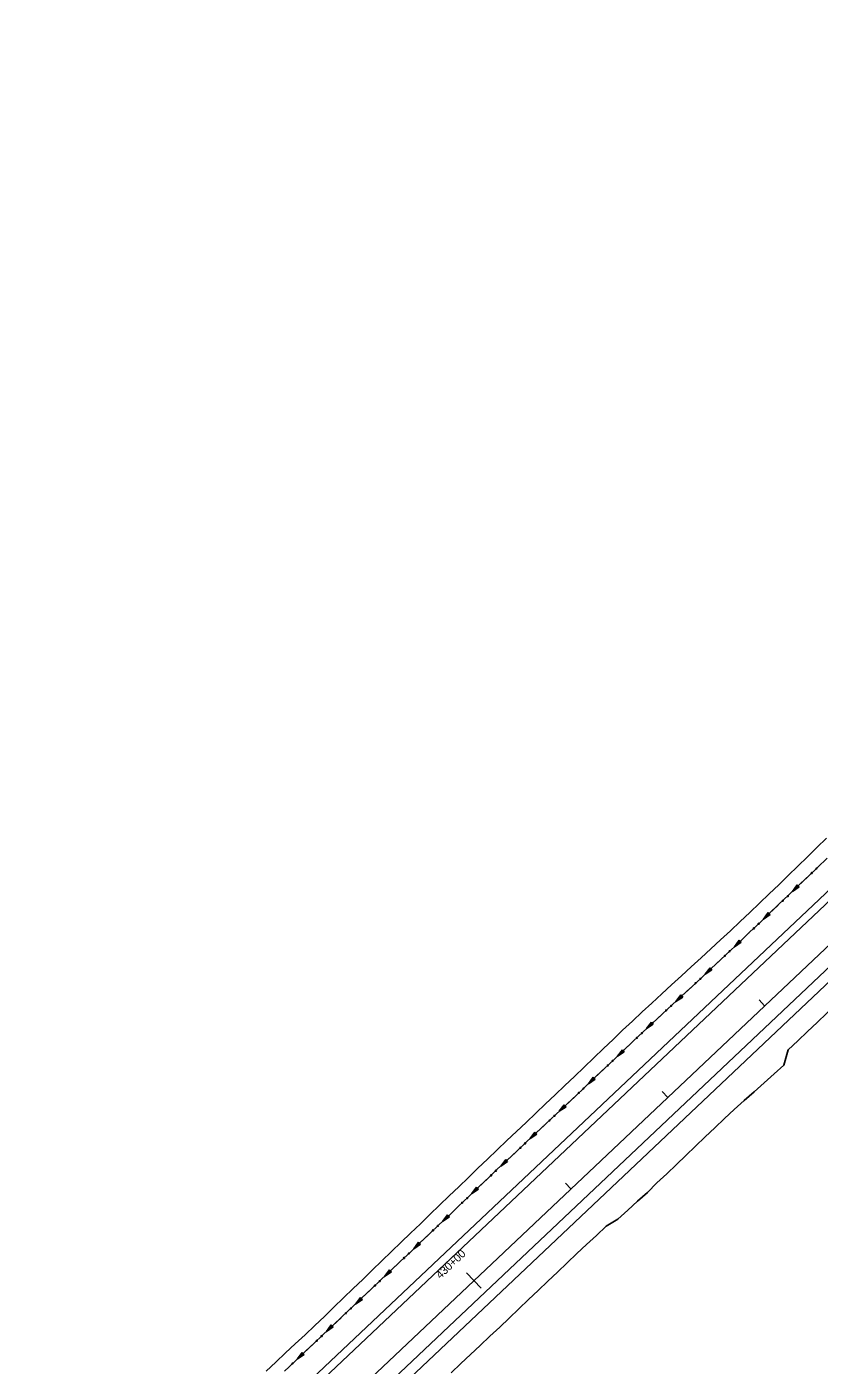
# Model space of a CAD drawing. Extents: x 1375694 to 1433473, y 1931050 to 1967991.
# Drawn here: x 1430411 to 1431005, y 1965367 to 1966371 of the extents above; entities that cross this region are included whole.
import ezdxf

# ---------------------------------------------------------------- set-up
doc = ezdxf.new("R2010")
doc.units = 0
for name, color, linetype in [('62', 7, 'Continuous'), ('R_Horz Alg', 7, 'Continuous'), ('R_Horz Alg Annot', 7, 'Continuous'), ('R_Proposed Const Limits', 7, 'Continuous'), ('R_Proposed Road', 7, 'Continuous')]:
    doc.layers.add(name, color=color, linetype=linetype)

msp = doc.modelspace()

# ---------------------------------------------------------------- linework, layer by layer
at = {"layer": '62'}
for p, q in [((1430989, 1965727.5), (1430985.4, 1965722.6)), ((1430985.4, 1965722.6), (1430990.4, 1965726)), ((1430990.4, 1965726), (1430989, 1965727.5)), ((1430967.2, 1965706.8), (1430963.6, 1965701.9)), ((1430963.6, 1965701.9), (1430968.7, 1965705.3)), ((1430968.7, 1965705.3), (1430967.2, 1965706.8)), ((1430945.5, 1965686.1), (1430941.8, 1965681.2)), ((1430941.8, 1965681.2), (1430946.9, 1965684.6)), ((1430946.9, 1965684.6), (1430945.5, 1965686.1)), ((1430923.6, 1965665.5), (1430919.9, 1965660.7)), ((1430925, 1965664), (1430923.6, 1965665.5)), ((1430919.9, 1965660.7), (1430925, 1965664)), ((1430901.6, 1965645.1), (1430897.9, 1965640.2)), ((1430903.1, 1965643.5), (1430901.6, 1965645.1)), ((1430897.9, 1965640.2), (1430903.1, 1965643.5)), ((1430879.6, 1965624.6), (1430875.9, 1965619.8)), ((1430881, 1965623.1), (1430879.6, 1965624.6)), ((1430875.9, 1965619.8), (1430881, 1965623.1)), ((1430857.8, 1965604), (1430854.1, 1965599.1)), ((1430859.2, 1965602.5), (1430857.8, 1965604)), ((1430854.1, 1965599.1), (1430859.2, 1965602.5)), ((1430836, 1965583.3), (1430832.3, 1965578.5)), ((1430832.3, 1965578.5), (1430837.4, 1965581.8)), ((1430837.4, 1965581.8), (1430836, 1965583.3)), ((1430814.1, 1965562.7), (1430810.5, 1965557.8)), ((1430810.5, 1965557.8), (1430815.6, 1965561.2)), ((1430815.6, 1965561.2), (1430814.1, 1965562.7)), ((1430792.2, 1965542.2), (1430788.6, 1965537.3)), ((1430788.6, 1965537.3), (1430793.7, 1965540.6)), ((1430793.7, 1965540.6), (1430792.2, 1965542.2)), ((1430770.3, 1965521.6), (1430766.7, 1965516.7)), ((1430766.7, 1965516.7), (1430771.7, 1965520.1)), ((1430771.7, 1965520.1), (1430770.3, 1965521.6)), ((1430748.5, 1965501), (1430744.9, 1965496.1)), ((1430744.9, 1965496.1), (1430749.9, 1965499.4)), ((1430749.9, 1965499.4), (1430748.5, 1965501)), ((1430726.7, 1965480.3), (1430723.1, 1965475.4)), ((1430723.1, 1965475.4), (1430728.2, 1965478.8)), ((1430728.2, 1965478.8), (1430726.7, 1965480.3)), ((1430704.9, 1965459.6), (1430701.3, 1965454.7)), ((1430701.3, 1965454.7), (1430706.4, 1965458.1)), ((1430706.4, 1965458.1), (1430704.9, 1965459.6)), ((1430683.1, 1965438.9), (1430679.5, 1965434)), ((1430679.5, 1965434), (1430684.6, 1965437.4)), ((1430684.6, 1965437.4), (1430683.1, 1965438.9)), ((1430661.4, 1965418.2), (1430657.7, 1965413.3)), ((1430657.7, 1965413.3), (1430662.8, 1965416.7)), ((1430662.8, 1965416.7), (1430661.4, 1965418.2)), ((1430639.5, 1965397.6), (1430635.9, 1965392.7)), ((1430635.9, 1965392.7), (1430641, 1965396.1)), ((1430641, 1965396.1), (1430639.5, 1965397.6)), ((1430617.7, 1965377), (1430614.1, 1965372.1)), ((1430614.1, 1965372.1), (1430619.1, 1965375.4)), ((1430619.1, 1965375.4), (1430617.7, 1965377))]:
    msp.add_line(p, q, dxfattribs=at)
for points in [[(1430604.3, 1965362.9), (1430611.6, 1965369.8), (1430618.9, 1965376.6), (1430626.2, 1965383.5), (1430633.4, 1965390.4), (1430640.7, 1965397.2), (1430648, 1965404.1), (1430655.2, 1965411), (1430662.5, 1965417.9), (1430669.7, 1965424.7), (1430677, 1965431.6), (1430684.2, 1965438.5), (1430691.5, 1965445.4), (1430698.8, 1965452.3), (1430706, 1965459.2), (1430713.3, 1965466.1), (1430720.5, 1965472.9), (1430727.8, 1965479.8), (1430735, 1965486.7), (1430742.3, 1965493.6), (1430749.5, 1965500.5), (1430756.8, 1965507.4), (1430764, 1965514.3), (1430771.3, 1965521.1), (1430778.6, 1965528), (1430785.9, 1965534.8), (1430793.2, 1965541.6), (1430800.5, 1965548.5), (1430807.8, 1965555.3), (1430815.1, 1965562.2), (1430822.3, 1965569), (1430829.6, 1965575.9), (1430836.9, 1965582.8), (1430844.1, 1965589.6), (1430851.4, 1965596.5), (1430858.6, 1965603.4), (1430865.9, 1965610.3), (1430873.2, 1965617.2), (1430880.5, 1965624), (1430887.8, 1965630.8), (1430895.1, 1965637.6), (1430902.5, 1965644.4), (1430909.8, 1965651.2), (1430917.1, 1965658), (1430924.4, 1965664.9), (1430931.7, 1965671.7), (1430939, 1965678.5), (1430946.3, 1965685.4), (1430953.5, 1965692.3), (1430960.8, 1965699.2), (1430968, 1965706.1), (1430975.2, 1965713), (1430982.5, 1965719.9), (1430989.7, 1965726.8), (1430996.9, 1965733.7), (1431004.1, 1965740.6), (1431011.3, 1965747.6)], [(1430996.2, 1965733), (1430989.7, 1965726.8), (1430985.4, 1965722.6)], [(1430996.2, 1965733), (1430996.2, 1965733)], [(1430974.5, 1965712.2), (1430968, 1965706.1), (1430963.6, 1965701.9)], [(1430974.5, 1965712.3), (1430974.5, 1965712.2)], [(1430952.7, 1965691.5), (1430946.3, 1965685.4), (1430941.8, 1965681.2)], [(1430952.8, 1965691.5), (1430952.7, 1965691.5)], [(1430930.9, 1965670.9), (1430924.4, 1965664.9), (1430919.9, 1965660.7)], [(1430930.9, 1965671), (1430930.9, 1965670.9)], [(1430908.9, 1965650.4), (1430902.5, 1965644.4), (1430897.9, 1965640.2)], [(1430909, 1965650.4), (1430908.9, 1965650.4)], [(1430886.9, 1965630), (1430880.5, 1965624), (1430875.9, 1965619.8)], [(1430887, 1965630), (1430886.9, 1965630)], [(1430865, 1965609.4), (1430858.6, 1965603.4), (1430854.1, 1965599.1)], [(1430865, 1965609.5), (1430865, 1965609.4)], [(1430843.2, 1965588.8), (1430836.9, 1965582.8), (1430832.3, 1965578.5)], [(1430843.2, 1965588.8), (1430843.2, 1965588.8)], [(1430821.4, 1965568.1), (1430815.1, 1965562.2), (1430810.5, 1965557.8)], [(1430821.4, 1965568.2), (1430821.4, 1965568.1)], [(1430799.5, 1965547.5), (1430793.2, 1965541.6), (1430788.6, 1965537.3)], [(1430799.5, 1965547.6), (1430799.5, 1965547.5)], [(1430777.6, 1965527), (1430771.3, 1965521.1), (1430766.7, 1965516.7)], [(1430777.6, 1965527), (1430777.6, 1965527)], [(1430755.7, 1965506.4), (1430749.5, 1965500.5), (1430744.9, 1965496.1)], [(1430755.8, 1965506.4), (1430755.7, 1965506.4)], [(1430734, 1965485.7), (1430727.8, 1965479.8), (1430723.1, 1965475.4)], [(1430734, 1965485.7), (1430734, 1965485.7)], [(1430712.2, 1965465), (1430706, 1965459.2), (1430701.3, 1965454.7)], [(1430712.2, 1965465.1), (1430712.2, 1965465)], [(1430690.4, 1965444.4), (1430684.2, 1965438.5), (1430679.5, 1965434)], [(1430690.4, 1965444.4), (1430690.4, 1965444.4)], [(1430668.6, 1965423.7), (1430662.5, 1965417.9), (1430657.7, 1965413.3)], [(1430668.6, 1965423.7), (1430668.6, 1965423.7)], [(1430646.8, 1965403), (1430640.7, 1965397.2), (1430635.9, 1965392.7)], [(1430646.8, 1965403), (1430646.8, 1965403)], [(1430625, 1965382.4), (1430618.9, 1965376.6), (1430614.1, 1965372.1)], [(1430625, 1965382.4), (1430625, 1965382.4)]]:
    msp.add_lwpolyline(points, dxfattribs=at)
for centre in [(1430999.8, 1965736.5), (1431003.4, 1965739.9), (1430978.1, 1965715.7), (1430981.8, 1965719.1), (1430956.4, 1965695), (1430960, 1965698.4), (1430934.6, 1965674.3), (1430938.2, 1965677.8), (1430912.6, 1965653.8), (1430916.3, 1965657.2), (1430894.3, 1965636.8), (1430890.6, 1965633.4), (1430872.3, 1965616.3), (1430868.7, 1965612.9), (1430850.5, 1965595.6), (1430846.9, 1965592.2), (1430828.7, 1965575), (1430825.1, 1965571.6), (1430806.8, 1965554.4), (1430803.2, 1965551), (1430784.9, 1965533.8), (1430781.3, 1965530.4), (1430763, 1965513.3), (1430759.4, 1965509.8), (1430737.6, 1965489.2), (1430741.3, 1965492.6), (1430715.8, 1965468.5), (1430719.5, 1965471.9), (1430694.1, 1965447.8), (1430697.7, 1965451.2), (1430672.3, 1965427.1), (1430675.9, 1965430.5), (1430650.5, 1965406.4), (1430654.1, 1965409.9), (1430628.6, 1965385.8), (1430632.3, 1965389.2), (1430610.4, 1965368.6)]:
    msp.add_circle(centre, 0.375, dxfattribs=at)
at = {"layer": 'R_Horz Alg'}
msp.add_line((1430431.8, 1965133.5), (1432780.4, 1967352.8), dxfattribs=at)
at = {"layer": 'R_Horz Alg Annot'}
for points in [[(1430960.4, 1965641.3), (1430964.5, 1965636.9)], [(1430887.7, 1965572.6), (1430891.9, 1965568.2)], [(1430815.1, 1965503.9), (1430819.2, 1965499.6)], [(1430741, 1965436.7), (1430752, 1965425.1)]]:
    msp.add_lwpolyline(points, dxfattribs=at)
at = {"layer": 'R_Proposed Const Limits'}
for points in [[(1430590.6, 1965362.9), (1430597.9, 1965369.7), (1430605.2, 1965376.6), (1430612.5, 1965383.4), (1430619.8, 1965390.2), (1430627.1, 1965397.1), (1430634.3, 1965404), (1430641.5, 1965411), (1430648.7, 1965417.9), (1430655.9, 1965424.9), (1430663.1, 1965431.8), (1430670.2, 1965438.8), (1430677.4, 1965445.7), (1430684.7, 1965452.6), (1430691.8, 1965459.6), (1430699, 1965466.5), (1430706.3, 1965473.5), (1430713.4, 1965480.4), (1430720.6, 1965487.4), (1430727.9, 1965494.3), (1430735.1, 1965501.2), (1430742.3, 1965508.1), (1430749.5, 1965515.1), (1430756.7, 1965522), (1430763.9, 1965528.9), (1430771.2, 1965535.8), (1430778.5, 1965542.7), (1430785.7, 1965549.5), (1430793, 1965556.4), (1430800.2, 1965563.3), (1430807.4, 1965570.2), (1430814.7, 1965577.1), (1430821.9, 1965584), (1430829.1, 1965591), (1430836.4, 1965597.9), (1430843.6, 1965604.8), (1430850.8, 1965611.7), (1430858, 1965618.7), (1430865.3, 1965625.5), (1430872.6, 1965632.3), (1430880, 1965639), (1430887.4, 1965645.8), (1430894.7, 1965652.6), (1430902.1, 1965659.3), (1430909.5, 1965666.1), (1430916.8, 1965672.9), (1430924.2, 1965679.7), (1430931.5, 1965686.4), (1430938.8, 1965693.2), (1430946.2, 1965700.1), (1430953.4, 1965706.9), (1430960.6, 1965713.9), (1430967.8, 1965720.8), (1430975.1, 1965727.7), (1430982.2, 1965734.7), (1430989.4, 1965741.6), (1430996.5, 1965748.7), (1431003.6, 1965755.7), (1431010.8, 1965762.7)], [(1430982.1, 1965603.8), (1430989.3, 1965610.7), (1430996.6, 1965617.6), (1431003.9, 1965624.4), (1431011.1, 1965631.3), (1431018.4, 1965638.2), (1431025.7, 1965645.1), (1431032.9, 1965651.9), (1431040.2, 1965658.8), (1431047.4, 1965665.7), (1431054.7, 1965672.6), (1431061.9, 1965679.5)], [(1430729.3, 1965361.8), (1430736.6, 1965368.6), (1430743.9, 1965375.4), (1430751.2, 1965382.3), (1430758.5, 1965389.1), (1430765.8, 1965395.9), (1430773, 1965402.8), (1430780.2, 1965409.7), (1430787.5, 1965416.6), (1430794.7, 1965423.5), (1430802, 1965430.4), (1430809.2, 1965437.3), (1430816.4, 1965444.2), (1430823.7, 1965451.1), (1430830.9, 1965458), (1430838.3, 1965464.8), (1430845.6, 1965471.6), (1430854.3, 1965477), (1430861.8, 1965483.6), (1430869.2, 1965490.3), (1430876.6, 1965497), (1430883.7, 1965504.1), (1430891.1, 1965510.8), (1430898.3, 1965517.8), (1430905.5, 1965524.7), (1430912.7, 1965531.7), (1430919.8, 1965538.7), (1430927.1, 1965545.5), (1430934.4, 1965552.4), (1430941.7, 1965559.1), (1430949.2, 1965565.8), (1430956.6, 1965572.5), (1430964.1, 1965579.2), (1430971.6, 1965585.8), (1430979, 1965592.5), (1430982.1, 1965603.8)]]:
    msp.add_lwpolyline(points, dxfattribs=at)
at = {"layer": 'R_Proposed Road'}
for p, q in [((1430411.1, 1965155.3), (1432759.8, 1967374.6)), ((1430415.3, 1965150.9), (1432763.9, 1967370.2)), ((1430440, 1965124.7), (1432788.7, 1967344.1)), ((1430445.5, 1965118.9), (1432794.2, 1967338.3))]:
    msp.add_line(p, q, dxfattribs=at)

# ---------------------------------------------------------------- texts
at = {"layer": 'R_Horz Alg Annot'}
msp.add_text('430+00', height=6, rotation=43.3781, dxfattribs=at).set_placement((1430721.3, 1965431.8))

doc.saveas('drawing.dxf')
